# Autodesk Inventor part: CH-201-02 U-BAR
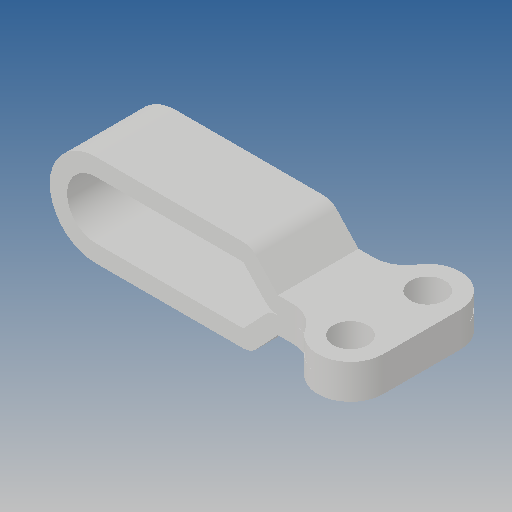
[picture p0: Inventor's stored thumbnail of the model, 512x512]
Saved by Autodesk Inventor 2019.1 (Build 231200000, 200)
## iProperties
Created: 2012-09
Part Number: CH-201-02 U-BAR
Material: Ogólny
Document SubType Name: Modeling
Designer: CADENGINEERING4
Density: 1 g/cm^3
Appearance: Domyślna
Author: CADENGINEERING4
Revision Number: ÈÎºÎ
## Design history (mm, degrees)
feature "ÇÐ³ý-À­Éì1"
feature "¾µÏò1"
node "Bryła1"
node "Bryła2"
